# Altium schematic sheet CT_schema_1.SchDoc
size 423 x 340 mm
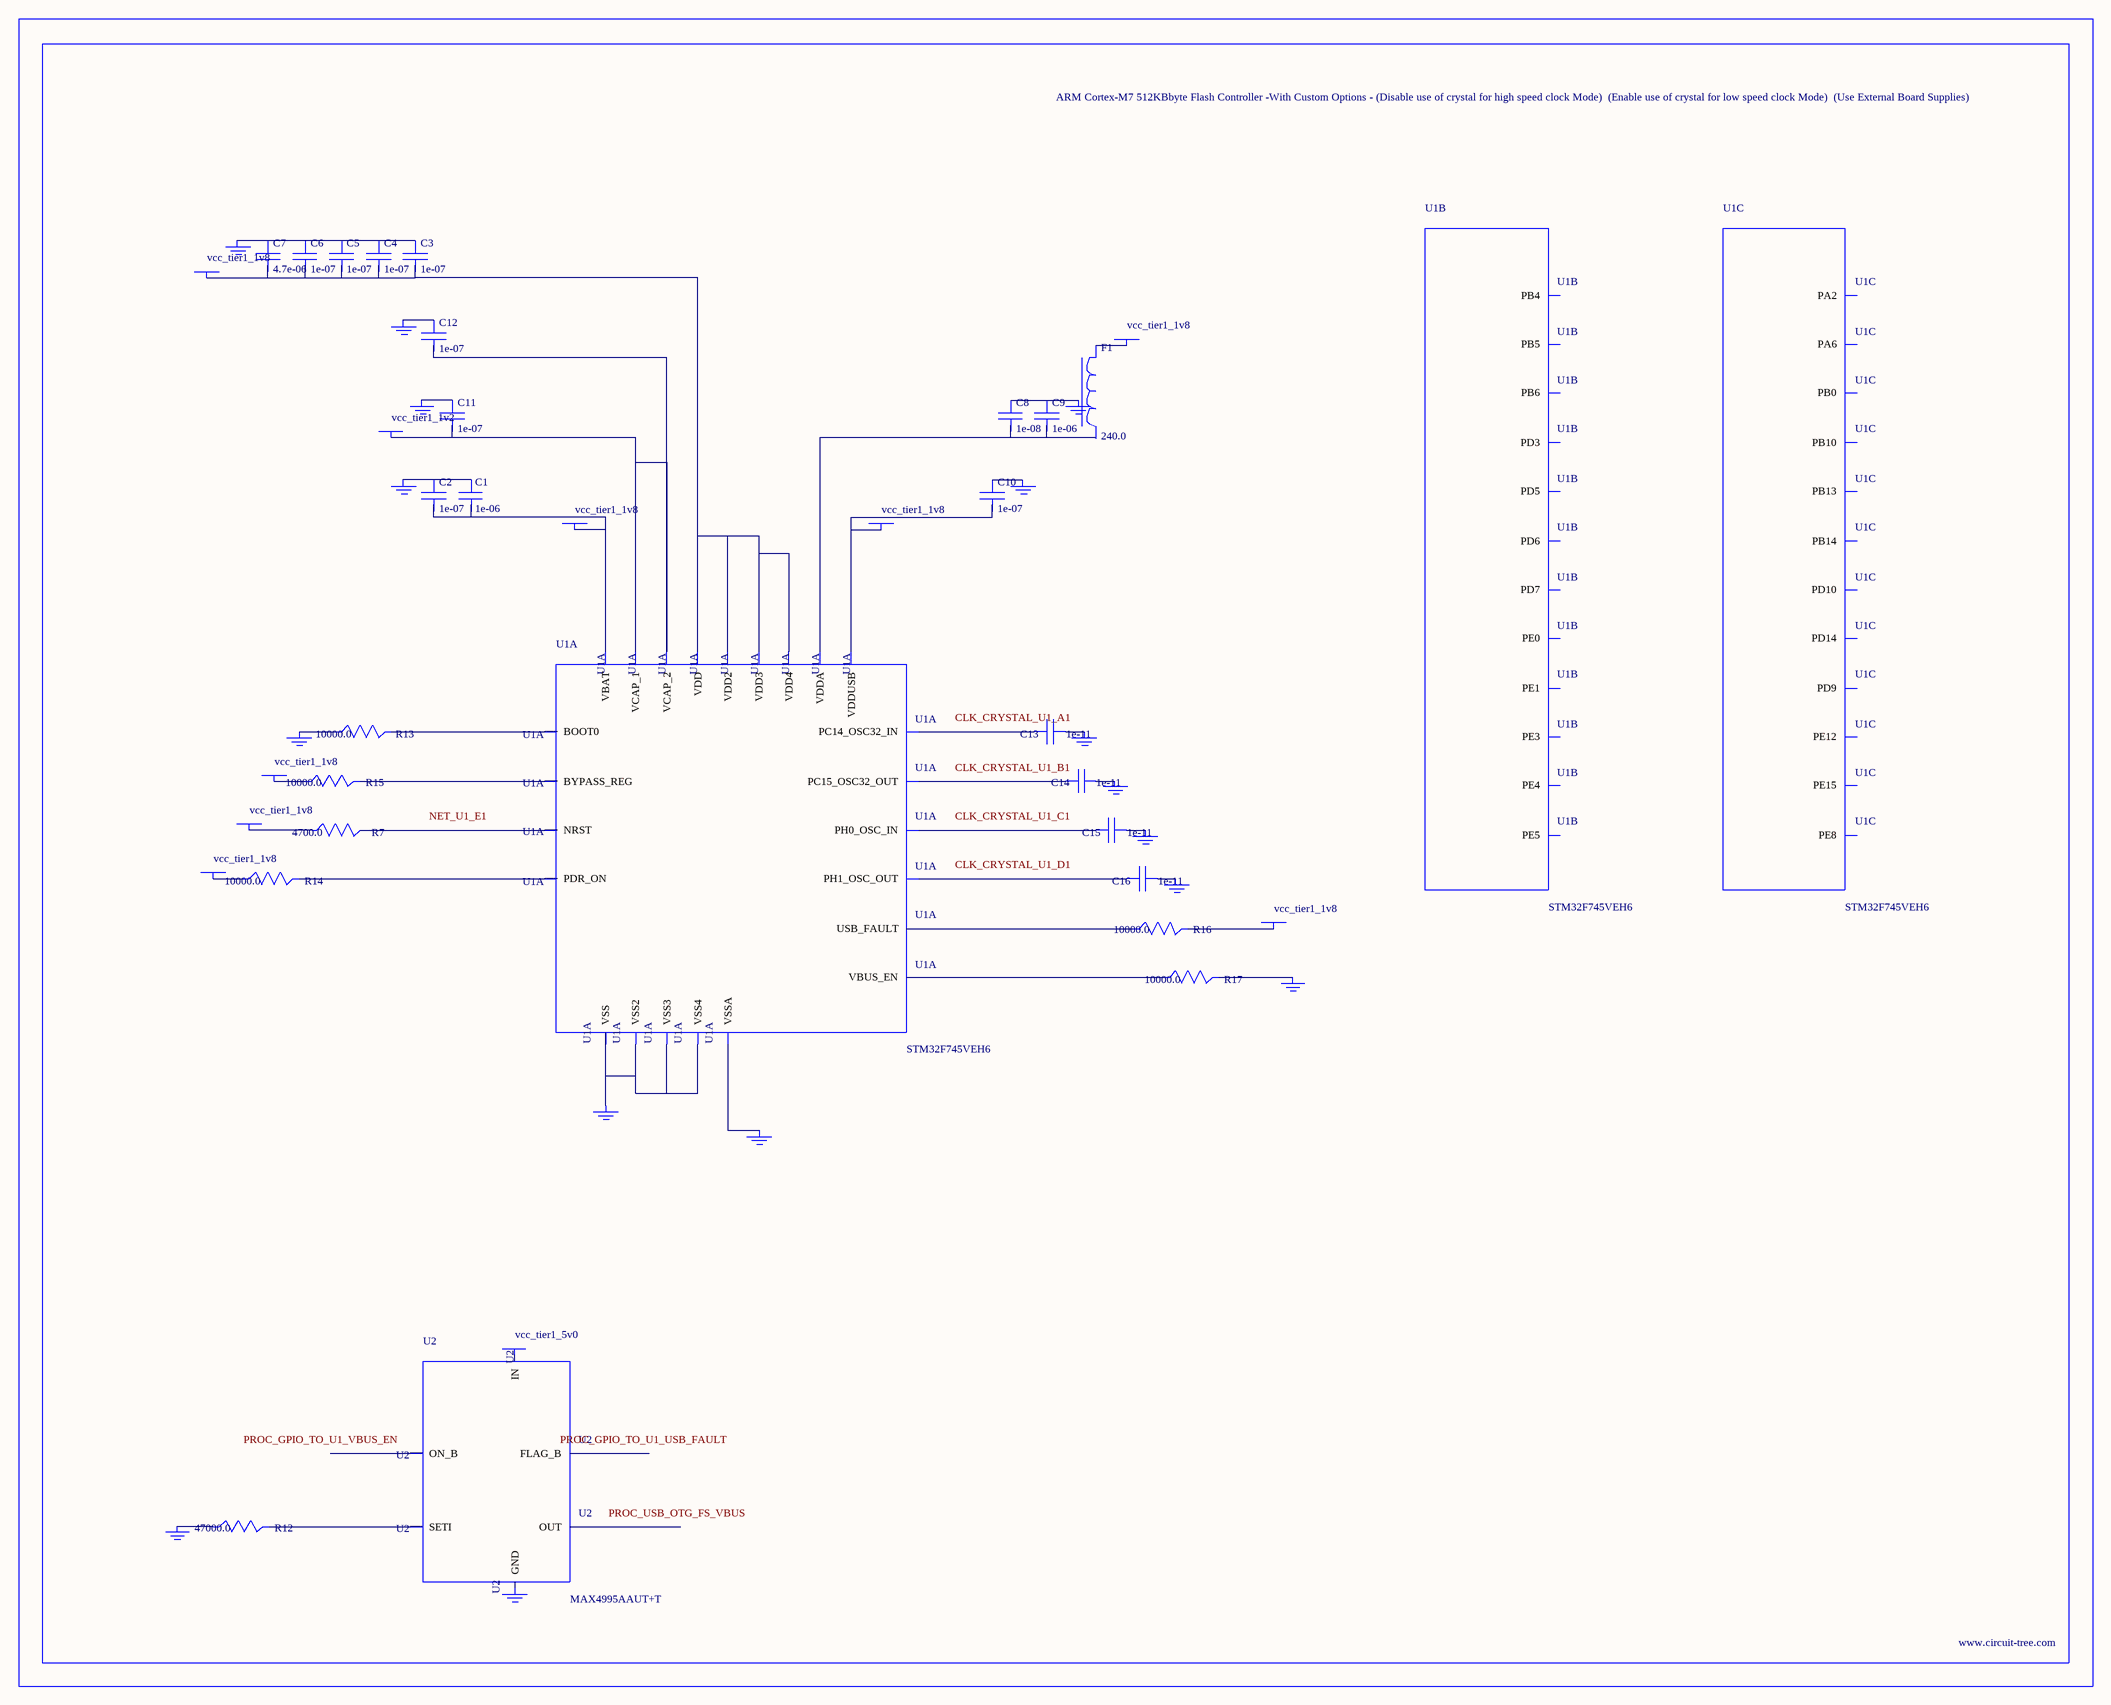
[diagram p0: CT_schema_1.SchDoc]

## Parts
BORDER0  (no value)
C1  1e-06  [C0603]
C2  1e-07  [C0603]
C3  1e-07  [C0603]
C4  1e-07  [C0603]
C5  1e-07  [C0603]
C6  1e-07  [C0603]
C7  4.7e-06  [C0603]
C8  1e-08  [C0603]
C9  1e-06  [C0603]
C10  1e-07  [C0603]
C11  1e-07  [C0603]
C12  1e-07  [C0603]
C13  1e-11  [C0402]
C14  1e-11  [C0402]
C15  1e-11  [C0402]
C16  1e-11  [C0402]
F1  240.0  [L0603]
GND_INSTANCE_0_0  (no value)
GND_INSTANCE_0_1  (no value)
GND_INSTANCE_0_2  (no value)
GND_INSTANCE_0_3  (no value)
GND_INSTANCE_0_4  (no value)
GND_INSTANCE_0_5  (no value)
GND_INSTANCE_0_6  (no value)
GND_INSTANCE_0_7  (no value)
GND_INSTANCE_0_8  (no value)
GND_INSTANCE_0_9  (no value)
GND_INSTANCE_0_10  (no value)
GND_INSTANCE_0_11  (no value)
GND_INSTANCE_0_12  (no value)
GND_INSTANCE_0_13  (no value)
GND_INSTANCE_0_14  (no value)
GND_INSTANCE_0_15  (no value)
POWER_INSTANCE_0_0  vcc_tier1_1v8
POWER_INSTANCE_0_1  vcc_tier1_1v8
POWER_INSTANCE_0_2  vcc_tier1_1v8
POWER_INSTANCE_0_3  vcc_tier1_1v8
POWER_INSTANCE_0_4  vcc_tier1_1v8
POWER_INSTANCE_0_5  vcc_tier1_1v8
POWER_INSTANCE_0_6  vcc_tier1_1v2
POWER_INSTANCE_0_7  vcc_tier1_1v8
POWER_INSTANCE_0_8  vcc_tier1_1v8
POWER_INSTANCE_0_9  vcc_tier1_5v0
R7  4700.0  [R0603]
R12  47000.0  [R0603]
R13  10000.0  [R0603]
R14  10000.0  [R0603]
R15  10000.0  [R0603]
R16  10000.0  [R0603]
R17  10000.0  [R0603]
U1  STM32F745VEH6  [TFBGA100]  (parts A,B,C of 10)
U2  MAX4995AAUT+T  [SOT-23-6]

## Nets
NetC1_1: C1.1 C2.1 GND_INSTANCE_0_0.0(GND)
NetC1_2: C1.2 C2.2 POWER_INSTANCE_0_0.0(PWR) U1.B2(VBAT)
NetC3_1: C3.1 C4.1 C5.1 C6.1 C7.1 GND_INSTANCE_0_2.0(GND)
NetC3_2: C3.2 C4.2 C5.2 C6.2 C7.2 POWER_INSTANCE_0_2.0(PWR) U1.D2(VDD) U1.F4(VDD2) U1.F5(VDD3) U1.K1(VDD4)
NetC8_1: C8.1 C9.1 GND_INSTANCE_0_1.0(GND)
NetC8_2: C8.2 C9.2 U1.H1(VDDA)
NetC10_1: C10.1 GND_INSTANCE_0_4.0(GND)
NetC10_2: C10.2 POWER_INSTANCE_0_4.0(PWR) U1.F6(VDDUSB)
NetC11_1: C11.1 GND_INSTANCE_0_5.0(GND)
NetC11_2: C11.2 C12.2 POWER_INSTANCE_0_6.0(PWR) U1.E7(VCAP_2) U1.F8(VCAP_1)
NetC12_1: C12.1 GND_INSTANCE_0_6.0(GND)
NetC13_1: C13.1 GND_INSTANCE_0_7.0(GND)
NetC13_2: C13.2 U1.A1(PC14_OSC32_IN)
NetC14_1: C14.1 GND_INSTANCE_0_8.0(GND)
NetC14_2: C14.2 U1.B1(PC15_OSC32_OUT)
NetC15_1: C15.1 GND_INSTANCE_0_9.0(GND)
NetC15_2: C15.2 U1.C1(PH0_OSC_IN)
NetC16_1: C16.1 GND_INSTANCE_0_10.0(GND)
NetC16_2: C16.2 U1.D1(PH1_OSC_OUT)
NetF1_1: F1.1 POWER_INSTANCE_0_1.0(PWR)
NetGND_INSTANCE_0_3_0: GND_INSTANCE_0_3.0(GND) R13.1
NetGND_INSTANCE_0_11_0: GND_INSTANCE_0_11.0(GND) R17.2
NetGND_INSTANCE_0_12_0: GND_INSTANCE_0_12.0(GND) U1.G1(VSSA)
NetGND_INSTANCE_0_13_0: GND_INSTANCE_0_13.0(GND) U1.C2(VSS) U1.E4(VSS2) U1.E5(VSS3) U1.J1(VSS4)
NetGND_INSTANCE_0_14_0: GND_INSTANCE_0_14.0(GND) R12.1
NetPOWER_INSTANCE_0_3_0: POWER_INSTANCE_0_3.0(PWR) R14.1
NetPOWER_INSTANCE_0_5_0: POWER_INSTANCE_0_5.0(PWR) R15.1
NetPOWER_INSTANCE_0_7_0: POWER_INSTANCE_0_7.0(PWR) R16.2
NetPOWER_INSTANCE_0_8_0: POWER_INSTANCE_0_8.0(PWR) R7.1
NetR7_2: R7.2 U1.E1(NRST)
NetR12_2: R12.2 U2.3(SETI)
NetR13_2: R13.2 U1.D5(BOOT0)
NetR14_2: R14.2 U1.F7(PDR_ON)
NetR15_2: R15.2 U1.E6(BYPASS_REG)
NetR16_1: R16.1 U1.A3(USB_FAULT)
NetR17_1: R17.1 U1.A2(VBUS_EN)

Not connected (* = marked no-connect by the designer): F1 2; GND_INSTANCE_0_15 0(GND); POWER_INSTANCE_0_9 0(PWR); U1 A6(PB4) B3(PE3) B5(PB6) B6(PD5) C3(PE4) C4(PE1) C5(PB5) C6(PD6) C7(PD3) D3(PE5) D4(PE0) D6(PD7) H7(PE15) H8(PD14) H9(PD10) H10(PB14) J2(PA2) J3(PA6) J4(PB0) J5(PE8) J6(PE12) J7(PB10) J8(PB13) J9(PD9); U2 1(OUT) 2(GND) 4(ON_B) 5(IN) 6(FLAG_B)

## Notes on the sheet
- Labels drawn without touching a wire or pin: CLK_CRYSTAL_U1_A1, CLK_CRYSTAL_U1_B1, CLK_CRYSTAL_U1_C1, CLK_CRYSTAL_U1_D1, NET_U1_E1, PROC_GPIO_TO_U1_USB_FAULT, PROC_GPIO_TO_U1_VBUS_EN, PROC_USB_OTG_FS_VBUS

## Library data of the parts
BORDER0 = BORDER_PAGE0
C1 C9 = C0603C105K3RACTU
C2-C6 C10-C12 = 06035C104K4Z2A
C7 = GRM188R6YA475KE15D
C8 = 06035C103K4Z2A
C13-C16 = C0402C100K3GACTU
F1 = Z0603C241ASMST
GND_INSTANCE_0_0-GND_INSTANCE_0_15 = GND
POWER_INSTANCE_0_0-POWER_INSTANCE_0_9 = PWR
R7 = RC0603JR-074K7L
R12 = RC0603JR-0747KL
R13-R17 = RC0603JR-0710KL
